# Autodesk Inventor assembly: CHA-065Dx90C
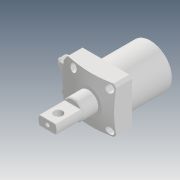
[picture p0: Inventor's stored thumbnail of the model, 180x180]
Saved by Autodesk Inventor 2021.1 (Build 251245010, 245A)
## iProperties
Created: 2019-12
Part Number: CHA-065Dx90C
Description: STEP AP203
Document SubType Name: Assembly
Designer: user
Title: CHA-065Dx90C.STEP
Revision Number: ÈÎºÎ
Sending System: SolidWorks 2017
Preprocessor: SwSTEP 2.0
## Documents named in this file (5)
- D:\Vault_2016\Projekty\Clamptek\Hydraulic\CHA\CHA\CHA-065\Inventor\CHA-065Dx90C\CHA-065Dx90C.iam
- D:\Vault_2016\Projekty\Clamptek\Hydraulic\CHA\CHA\CHA-065\Inventor\CHA-065Dx90C\CHA-065±¾Ìå.ipt
- D:\Vault_2016\Projekty\Clamptek\Hydraulic\CHA\CHA\CHA-065\Inventor\CHA-065Dx90C\CHA-065D(Ë«±Û£©»îÈû¸Ë.ipt
- D:\Vault_2016\Projekty\Clamptek\Hydraulic\CHA\CHA\CHA-065\Inventor\CHA-065Dx90C\G1-4¶ÂÍ·.ipt
- D:\Vault_2016\Projekty\Clamptek\Hydraulic\CHA\CHA\CHA-065\Inventor\CHA-065Dx90C\CZL20µ÷ËÙ·§.iam
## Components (4 placed, 4 different names)
1. CHA-065±¾Ìå_1
2. CHA-065D(Ë«±Û£©»îÈû¸Ë_2
3. G1-4¶ÂÍ·_3
4. CZL20µ÷ËÙ·§_4 [sub-assembly]
